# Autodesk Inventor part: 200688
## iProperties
Created: 2007-11
Part Number: 200688
Document SubType Name: Modeling
Designer: TH
Density: 7.85 g/cm^3
Mass: 313.071 g
Surface Area: 247.504 cm^2
Volume: 39.8817 cm^3
Material: Steel
Description: BACK SUPPORT PLATE
Component Category: Lower Component
Author: TH
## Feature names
1. Extrusion1
2. Fillet1
3. Fillet2
4. Fillet3
5. Extrusion2
6. Fillet4
7. Extrusion3
8. Extrusion7
9. Extrusion8
10. Fillet11
11. Fillet12
12. Fillet13
13. Extrusion9
14. Extrusion10
15. Extrusion11
16. Fillet14
17. Fillet15
18. Fillet16
19. Fillet18
20. Extrusion12
21. Fillet19
22. Fillet20
23. Fillet21
24. Fillet22
25. Fillet23
26. Extrusion13
27. Fillet25
28. Extrusion14
29. Fillet26
30. Fillet27
31. Fillet28
32. Hole1
33. Extrusion15
34. Extrusion16
35. Extrusion17
36. Fillet29
37. Chamfer1
38. Hole3
39. Extrusion18
40. Fillet30
41. Extrusion19
